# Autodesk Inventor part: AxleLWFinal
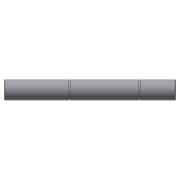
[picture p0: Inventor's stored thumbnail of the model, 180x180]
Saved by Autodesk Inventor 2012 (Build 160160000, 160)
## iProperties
Created: 2010-12
Part Number: AxleLWFinal
Document SubType Name: Modeling
Designer: Alex
Density: 2.71 g/cm^3
Material: Aluminum-6061
Mass: 33.5953 g
Surface Area: 49.1218 cm^2
Volume: 12.3968 cm^3
Author: Alex
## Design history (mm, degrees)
sketch "Sketch1"
  geometry: L1 (103.188, 0)-(0, 0); L2 (0, 0)-(0, 5.953); L3 (103.187, 5.953)-(103.188, 0); L4 (81.826, 6.35)-(81.826, 5.944); L5 (81.826, 5.944)-(80.835, 5.944); L6 (80.835, 5.944)-(80.835, 6.35); L7 (11.049, 6.35)-(11.049, 5.944); L8 (11.049, 5.944)-(10.058, 5.944); L9 (10.058, 5.944)-(10.058, 6.35); L10 (0.397, 6.35)-(10.058, 6.35); L11 (81.826, 6.35)-(102.791, 6.35); L12 (0, 5.953)-(0.397, 6.35); L13 (103.187, 5.953)-(102.791, 6.35); L14 (39.764, 6.35)-(39.764, 5.944); L15 (39.764, 5.944)-(38.773, 5.944); L16 (38.773, 5.944)-(38.773, 6.35); L17 (11.049, 6.35)-(38.773, 6.35); L18 (39.764, 6.35)-(80.835, 6.35); L19 (11.049, 6.35)-(10.058, 6.35); 3 further points
  constraints: 40 end point, 8 parallel, 7 collinear, 4 point on line, 1 coincident, 1 horizontal, 1 perpendicular, 1 vertical
  dimensions: "d56" = 103.1875 distance between parallel lines of L3 L2; "d57" = 5.9436 distance between parallel lines of L1 L8; "d58" = 0.9906 distance between parallel lines of L7 L9; "d59" = 11.049 distance from line of L7.end L2; "d60" = 0.9906 distance between parallel lines of L4 L6; "d61" = 22.352 distance between parallel lines of L6 L3; "d77" = 0.39687 distance of L2.end point (0, 6.35); "d78" = 0.39687 distance of L10.start point (0, 6.35) (= d77); "d79" = 0.39687 distance of L3.start point (103.188, 6.35); "d80" = 0.39687 distance of L11.end point (103.188, 6.35) (= d79); "d81" = 0.9906 distance between parallel lines of L14 L16; "d83" = 6.35 distance between parallel lines of L1 L10; "d84" = 41.0718 distance between parallel lines of L6 L14
revolve "Revolution3" sketch "Sketch1" stored, may be unused: angle "d62" = 90 deg
sketch "Sketch15"
  geometry: C1 r 5.953 at (0, 0); C2 r 5.953 at (0, 0) reference; 1 further point
  constraints: 1 centre point, 1 coincident
hole "Hole4" sketch "Sketch15" at (0, 0) diameter "d63" = 4.9784; stored, may be unused: countersink angle "d67" = 82 deg, drill point angle "d69" = 118 deg; dims "d64" = 9.525, "d65" = 9.525, "d66" = 6.35, "d68" = 15.875
sketch "Sketch16"
  geometry: 1 further point
hole "Hole5" sketch "Sketch16" at (0, 0) diameter "d70" = 4.9784; stored, may be unused: countersink angle "d74" = 82 deg, drill point angle "d76" = 118 deg; dims "d71" = 9.525, "d72" = 9.525, "d73" = 6.35, "d75" = 15.875
body "Solid2"
